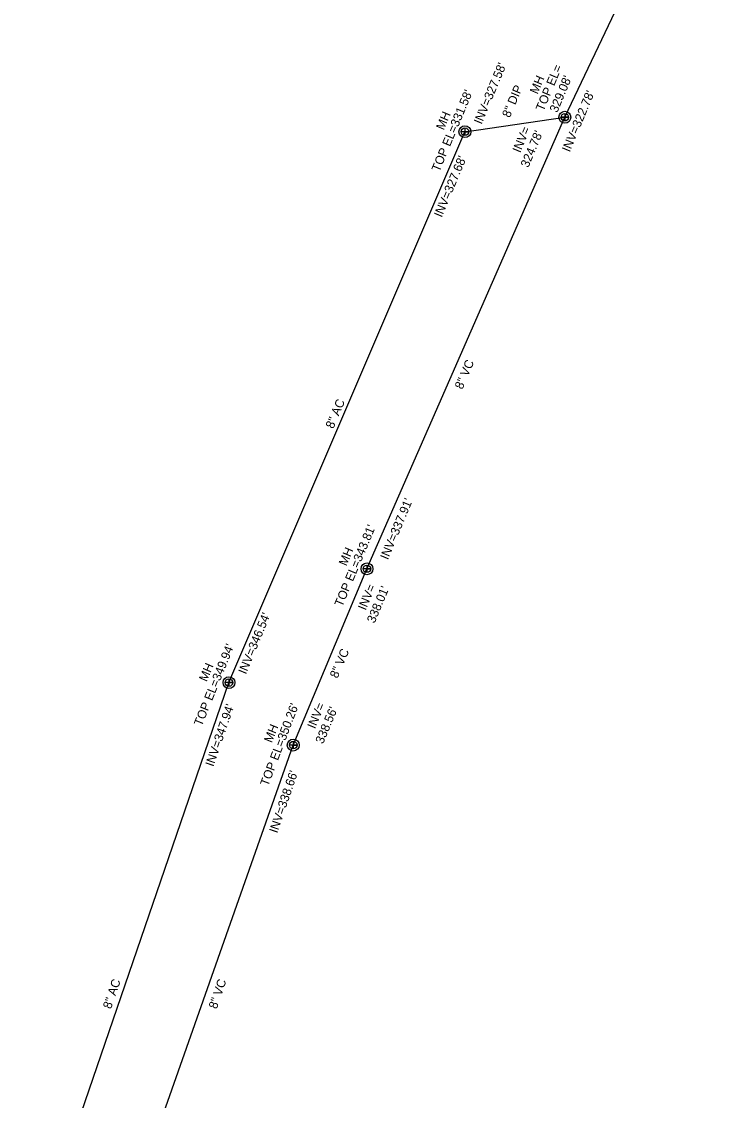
# Model space of a CAD drawing. Extents: x 1975698 to 1978521, y 778259 to 782969.
# Drawn here: x 1977555.8 to 1977873.6, y 781501.2 to 781991.2 of the extents above; entities that cross this region are included whole.
import ezdxf

# ---------------------------------------------------------------- set-up
doc = ezdxf.new("R2010")
doc.units = 0
for name, color, linetype in [('Old_Level_11', 7, 'Continuous'), ('Prop Horizontal Alignment', 7, 'Continuous'), ('Prop Horizontal Alignment Station Label', 7, 'Continuous'), ('Prop WCC CELL', 7, 'Continuous')]:
    doc.layers.add(name, color=color, linetype=linetype)

# ---------------------------------------------------------------- blocks, each defined once
blk = doc.blocks.new('EXIST UTILITIES SANITARY SEWER MANHOLE')
at = {"layer": 'Prop Horizontal Alignment'}
blk.add_lwpolyline([(0, 0.0342), (0, -0.0342), (0, 0), (0.0342, 0), (-0.0342, 0)], dxfattribs=at)
for radius in [0.0539, 0.0342]:
    blk.add_circle((0, 0), radius, dxfattribs=at)

msp = doc.modelspace()

# ---------------------------------------------------------------- linework, layer by layer
at = {"layer": 'Prop Horizontal Alignment Station Label'}
for p, q in [((1977802.51, 781947.79), (1977873.64, 782097.11)), ((1977712.64, 781742.68), (1977802.51, 781947.79)), ((1977757.14, 781941.21), (1977802.51, 781947.79)), ((1977649.96, 781690.99), (1977757.14, 781941.21)), ((1977679.17, 781662.62), (1977712.64, 781742.68)), ((1977555.78, 781416.47), (1977649.96, 781690.99)), ((1977602.55, 781445), (1977679.17, 781662.62))]:
    msp.add_line(p, q, dxfattribs=at)

# ---------------------------------------------------------------- block references
at = {"layer": 'Prop Horizontal Alignment', "xscale": 50, "yscale": 50}
for p in [(1977802.51, 781947.79), (1977757.14, 781941.21), (1977712.64, 781742.68), (1977649.96, 781690.99), (1977679.17, 781662.62)]:
    msp.add_blockref('EXIST UTILITIES SANITARY SEWER MANHOLE', p, dxfattribs=at)

# ---------------------------------------------------------------- texts
at = {"layer": 'Old_Level_11'}
for s, rotation, p in [('8" DIP', 66.8129, (1977777.48, 781947.28)), ('8" VC', 66.8129, (1977755.98, 781823.9)), ('8" AC', 66.8129, (1977697.32, 781806.03)), ('8" VC', 66.8129, (1977699.24, 781692.67)), ('8" AC', 71.0024, (1977596.36, 781542.51)), ('8" VC', 71.0024, (1977644.38, 781542.49))]:
    msp.add_text(s, height=4, rotation=rotation, dxfattribs=at).set_placement(p)
at = {"layer": 'Prop WCC CELL'}
for s, rotation, p in [("INV=327.58'", 67.3112, (1977764.69, 781944.3)), ('TOP EL=', 67.3112, (1977792.82, 781950.22)), ('MH', 66.8967, (1977790.1, 781957.99)), ("329.08'", 67.3112, (1977799.06, 781949.59)), ("TOP EL=331.58'", 67.3112, (1977745.51, 781922.69)), ("INV=322.78'", 67.3112, (1977804.74, 781931.67)), ('MH', 66.8967, (1977747.52, 781941.66)), ('INV=', 67.3112, (1977782.24, 781931.36)), ("324.78'", 67.3112, (1977785.93, 781924.63)), ("INV=327.68'", 67.3112, (1977746.59, 781902.02)), ("INV=337.91'", 67.3112, (1977722.15, 781746.52)), ("TOP EL=343.81'", 67.3112, (1977701.41, 781725.15)), ('MH', 66.8967, (1977703.31, 781743.69)), ('INV=', 67.3112, (1977712.03, 781723.55)), ("338.01'", 67.3112, (1977716.1, 781717.72)), ("INV=346.54'", 67.6908, (1977657.71, 781694.5)), ("TOP EL=349.94'", 67.995, (1977637.6, 781670.92)), ('MH', 66.5352, (1977639.81, 781691.14)), ("INV=347.94'", 71.0168, (1977642.88, 781652.58)), ("TOP EL=350.26'", 69.2815, (1977667.75, 781643.68)), ('INV=', 67.3112, (1977689.05, 781669.73)), ("338.56'", 67.3112, (1977692.7, 781662.91)), ('MH', 68.0038, (1977669.39, 781663.39)), ("INV=338.66'", 71.1267, (1977671.88, 781622.37))]:
    msp.add_text(s, height=4, rotation=rotation, dxfattribs=at).set_placement(p)

doc.saveas('drawing.dxf')
